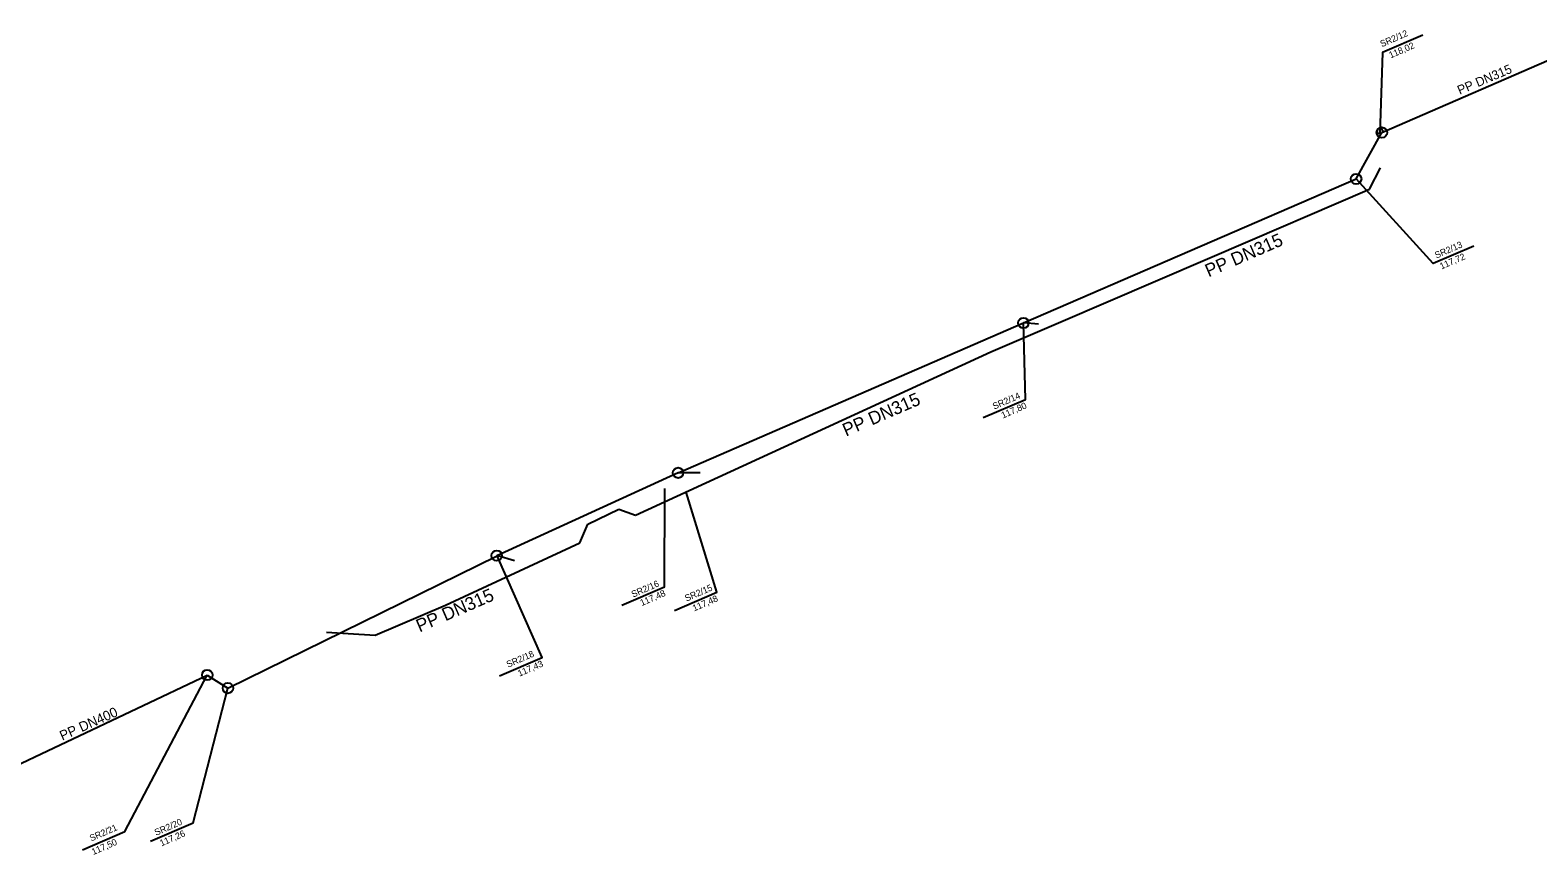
# Model space of a CAD drawing. Extents: x 7499288 to 7500494, y 5768505 to 5769051.
# Drawn here: x 7499589.5 to 7499762.8, y 5768627.1 to 5768721.9 of the extents above; entities that cross this region are included whole.
import ezdxf

# ---------------------------------------------------------------- set-up
doc = ezdxf.new("R2010")
doc.units = 0
for name, color, linetype in [('1_proj_kd_etap2', 7, 'Continuous'), ('1_proj_wodociąg', 7, 'Continuous'), ('2_opisy_etap2', 7, 'Continuous'), ('2_opisy_KD_etap1', 7, 'Continuous')]:
    doc.layers.add(name, color=color, linetype=linetype)

msp = doc.modelspace()

# ---------------------------------------------------------------- linework, layer by layer
at = {"layer": '1_proj_kd_etap2'}
for p, q in [((7499744.91, 5768710.09), (7499768.03, 5768720.15)), ((7499741.95, 5768704.76), (7499744.91, 5768710.09)), ((7499703.69, 5768688.2), (7499741.95, 5768704.76)), ((7499663.98, 5768670.98), (7499703.69, 5768688.2)), ((7499705.44, 5768688.06), (7499703.69, 5768688.2)), ((7499663.98, 5768670.98), (7499643.16, 5768661.45)), ((7499666.52, 5768670.96), (7499663.98, 5768670.98)), ((7499612.22, 5768646.23), (7499643.17, 5768661.45)), ((7499645.16, 5768660.88), (7499643.13, 5768661.46)), ((7499582.73, 5768634.9), (7499609.85, 5768647.74)), ((7499609.85, 5768647.74), (7499612.22, 5768646.23))]:
    msp.add_line(p, q, dxfattribs=at)
for centre, radius in [((7499744.91, 5768710.09), 0.6), ((7499744.68, 5768710.26), 0.311), ((7499741.95, 5768704.76), 0.6), ((7499703.69, 5768688.2), 0.6), ((7499663.98, 5768670.98), 0.6), ((7499643.13, 5768661.46), 0.6), ((7499609.85, 5768647.74), 0.6), ((7499612.22, 5768646.23), 0.6)]:
    msp.add_circle(centre, radius, dxfattribs=at)
at = {"layer": '1_proj_wodociąg'}
for p, q in [((7499743.48, 5768703.58), (7499744.76, 5768706.02)), ((7499739.65, 5768701.94), (7499743.48, 5768703.58)), ((7499730.02, 5768697.8), (7499739.65, 5768701.94)), ((7499708, 5768688.35), (7499730.02, 5768697.8)), ((7499699.93, 5768684.88), (7499708, 5768688.35)), ((7499659.08, 5768666.12), (7499699.93, 5768684.88)), ((7499653.59, 5768665.09), (7499657.19, 5768666.8)), ((7499657.19, 5768666.8), (7499659.08, 5768666.12)), ((7499652.67, 5768662.94), (7499653.59, 5768665.09)), ((7499637.23, 5768655.78), (7499652.67, 5768662.94)), ((7499629.15, 5768652.31), (7499637.23, 5768655.78)), ((7499623.56, 5768652.68), (7499629.15, 5768652.31))]:
    msp.add_line(p, q, dxfattribs=at)
at = {"layer": '2_opisy_KD_etap1'}
for points in [[(7499749.63, 5768721.28), (7499744.97, 5768719.29), (7499744.69, 5768709.97)], [(7499755.47, 5768697.02), (7499750.81, 5768695.03), (7499741.95, 5768704.76)], [(7499699.06, 5768677.32), (7499703.94, 5768679.41), (7499703.69, 5768688.2)], [(7499657.53, 5768655.77), (7499662.41, 5768657.86), (7499662.46, 5768669.16)], [(7499663.56, 5768655.16), (7499668.44, 5768657.25), (7499664.93, 5768668.76)], [(7499643.46, 5768647.65), (7499648.34, 5768649.74), (7499643.17, 5768661.45)], [(7499595.5, 5768627.65), (7499600.38, 5768629.74), (7499609.85, 5768647.74)], [(7499603.33, 5768628.64), (7499608.21, 5768630.73), (7499612.22, 5768646.23)]]:
    msp.add_lwpolyline(points, dxfattribs=at)

# ---------------------------------------------------------------- texts
at = {"layer": '2_opisy_etap2'}
msp.add_text('PP DN400', height=1.125, rotation=24.0293, dxfattribs=at).set_placement((7499593.18, 5768640.18))
at = {"layer": '2_opisy_KD_etap1'}
for s, height, rotation, p in [('SR2/12', 0.75, 23.5988, (7499744.91, 5768719.89)), ('118,02', 0.75, 23.5988, (7499745.92, 5768718.6)), ('PP DN315', 1.05, 22.9552, (7499753.86, 5768714.42)), ('PP DN315', 1.5, 23.3875, (7499724.98, 5768693.44)), ('SR2/13', 0.75, 23.5988, (7499751.18, 5768695.6)), ('117,72', 0.75, 23.5988, (7499751.76, 5768694.34)), ('PP DN315', 1.5, 23.3875, (7499683.29, 5768675.13)), ('SR2/14', 0.75, 23.5988, (7499700.34, 5768678.24)), ('117,80', 0.75, 23.5988, (7499701.34, 5768677.21)), ('PP DN315', 1.5, 23.3981, (7499634.26, 5768652.62)), ('SR2/16', 0.75, 23.5988, (7499658.81, 5768656.63)), ('117,48', 0.75, 23.5988, (7499659.81, 5768655.65)), ('SR2/15', 0.75, 23.5988, (7499664.95, 5768656.17)), ('117,48', 0.75, 23.5988, (7499665.84, 5768655.04)), ('SR2/18', 0.75, 23.5988, (7499644.44, 5768648.57)), ('117,43', 0.75, 23.5988, (7499645.74, 5768647.54)), ('SR2/20', 0.75, 23.5988, (7499603.97, 5768629.25)), ('SR2/21', 0.75, 23.5988, (7499596.51, 5768628.6)), ('117,26', 0.75, 23.5988, (7499604.58, 5768628.03)), ('117,50', 0.75, 23.5988, (7499596.74, 5768627.04))]:
    msp.add_text(s, height=height, rotation=rotation, dxfattribs=at).set_placement(p)

doc.saveas('drawing.dxf')
